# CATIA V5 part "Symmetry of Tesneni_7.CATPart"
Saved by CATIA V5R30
Part number: Symmetry of Tesneni_7
Bounding box of the stored display mesh (mm): x 0 to 1.2, y -6 to 6, z -6 to 6
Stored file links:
  E:\Bakalarka\Model\Forma_v7\Symmetry of Tesneni_7.CATPart
  E:\Bakalarka\Model\Forma_v7\Tesneni.CATPart
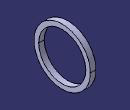
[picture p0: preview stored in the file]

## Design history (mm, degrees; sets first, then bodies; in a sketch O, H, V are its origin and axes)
Body1 (main body)
  Body2 "Body from original PartBody"
    Solid1: linked copy from another document
  Assemble1: tool Body2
